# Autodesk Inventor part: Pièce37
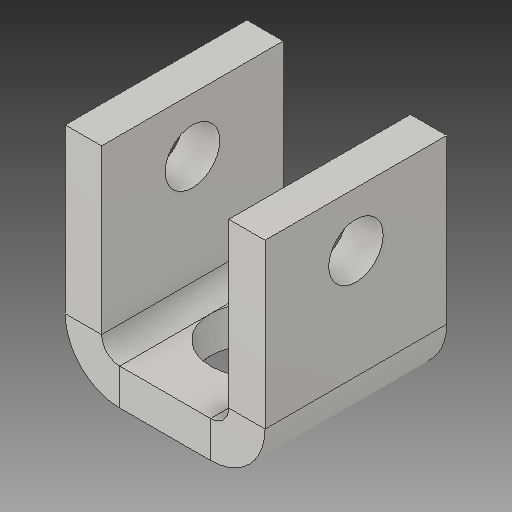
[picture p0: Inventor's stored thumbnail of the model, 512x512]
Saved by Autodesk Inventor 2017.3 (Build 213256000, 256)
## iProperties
Created: 2007-12
Part Number: Pièce37
Material: Générique
Document SubType Name: Modeling
Designer: ficho
Density: 1 g/cm^3
Appearance: Par défaut
Author: ficho
Sending System: SolidWorks 2009
Last Author: christophe
Last Saved: 2011-02-10
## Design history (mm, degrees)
feature "Enlèv. mat.-Extru.3"
node "Solide1"
